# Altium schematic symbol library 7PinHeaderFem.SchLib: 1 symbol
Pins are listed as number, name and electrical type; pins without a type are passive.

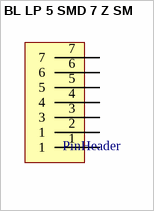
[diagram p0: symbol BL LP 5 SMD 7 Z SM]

## BL LP 5 SMD 7 Z SM
designator PinHeader
Fischer elektronik 7 pin female header. SMD.
footprint BL LP 5 SMD 7 Z SM (Fischer elektronik 7 pin female header. SMD.)
pins: 1, 2 1, 3, 4, 5, 6, 7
